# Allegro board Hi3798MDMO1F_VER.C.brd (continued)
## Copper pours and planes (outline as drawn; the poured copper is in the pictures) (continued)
1V1_CORE on BOTTOM (solid shape): 85.54,35.51 88.44,35.51 88.57,35.38 88.57,32.83 88.49,32.76 84.81,32.76 84.66,32.91 83.26,32.91 82.96,33.22 82.96,33.34 84.58,33.34 84.58,33.72 84.2,33.72 84.2,33.34 82.96,33.34 82.96,36.24 81.66,37.53 81.66,37.99 81.74,38.07 82.98,38.07
1V1_CPU on TOP (solid shape): 101.78,58.11 101.78,53.99 101.44,53.65 89.83,53.65 89.28,53.1 88.7,53.1 88.16,52.57 86.13,52.57 85.88,52.32 85.5,52.32 84.99,51.81 83.21,51.81 82.93,51.53 82.73,51.53 82.63,51.63 82.63,52.62 82.76,52.76 82.79,52.75 82.84,52.74 82.89,52.74 82.94,52.75 82.98,52.77 83.03,52.79 83.05,52.8 84.73,52.8 84.76,52.82 84.76,52.9 88.01,52.9 88.01,53.28 87.63,53.28 87.63,52.9 87.38,52.9 87.38,53.28 86.61,53.28 86.61,52.9 86.36,52.9 86.36,53.28 85.98,53.28 85.98,52.9 84.76,52.9 84.76,53.36 84.71,53.41 83.04,53.41 83.01,53.43 82.96,53.44 82.91,53.45 82.87,53.46 82.82,53.45 82.77,53.45 82.65,53.56 82.65,53.84 82.8,53.99 84.73,53.99 84.81,54.07 84.81,54.83 84.91,54.93 86.77,54.93 87.81,55.98 94.59,55.98 94.72,56.1 94.72,58.72 94.89,58.89 100.99,58.89
1V1_CPU on BOTTOM (solid shape): 99.14,56.12 99.14,56.12 99.32,55.95 99.32,53.87 99.09,53.64 93.75,53.64 93.6,53.79 93.6,54.81 97.28,54.81 97.28,55.19 96.9,55.19 96.9,54.81 93.6,54.81 93.6,55.57 93.65,55.62 97.46,55.62 97.66,55.82 97.66,56.58 97.79,56.71 98.55,56.71
1V1_CPU on BOTTOM (solid shape): 86.44,54.86 86.44,52.25 86.33,52.15 85.86,52.15 85.81,52.2 85.77,52.23 85.72,52.25 85.67,52.26 85.62,52.27 85.57,52.27 85.52,52.27 85.47,52.25 85.43,52.23 85.39,52.2 85.35,52.17 85.32,52.13 85.29,52.09 85.27,52.04 85.25,51.99 83.29,51.99 82.88,51.58 81.84,51.58 81.79,51.63 81.79,51.76 82.55,51.76 82.55,52.14 82.17,52.14 82.17,51.76 81.79,51.76 81.79,52.39 84.2,52.39 84.2,52.77 83.57,52.77 83.57,52.39 81.79,52.39 81.79,52.69 81.84,52.74 83.01,52.74 83.16,52.9 86.11,52.9 86.11,53.54 85.73,53.54 85.73,52.9 83.16,52.9 83.22,52.95 83.22,53.25 83.01,53.46 81.84,53.46 81.79,53.51 81.79,53.54 84.58,53.54 84.58,53.79 86.11,53.79 86.11,54.42 85.73,54.42 85.73,53.79 84.58,53.79 84.58,53.92 84.2,53.92 84.2,53.54 81.79,53.54 81.79,53.79 82.55,53.79 82.55,53.92 82.17,53.92 82.17,53.79 81.79,53.79 81.79,54.02 81.86,54.09 83.26,54.09 83.49,54.32 84.45,54.32 84.47,54.34 84.9,54.34 85.45,54.88 86.41,54.88
1V5_DDR3 on TOP (solid shape): 16.11,60.41 16.71,59.81 16.71,53.61 16.36,53.26 13.8,53.26 13.74,53.32 13.74,55.07 16.28,55.07 16.28,55.32 15.93,55.32 15.93,55.07 13.74,55.07 13.74,55.57 16.26,55.57 16.26,55.95 15.88,55.95 15.88,55.57 13.74,55.57 13.74,56.05 13.56,56.23 13.56,60.14 13.83,60.41 15.29,60.41
1V5_DDR3 on TOP (solid shape): outline of 129 points within 56.67,35.04 81.53,58.13
1V5_DDR3 on BOTTOM (solid shape): outline of 582 points within 14.99,30.55 59.41,63.83
3V3 on TOP (solid shape): 127.89,51.3 127.89,47.67 127.89,47.66 127.89,27.63 125.48,25.21 125.48,20.14 125.22,19.89 123.57,19.89 123.41,20.06 123.41,25.66 125.68,27.94 125.68,49.93 122.71,52.9 122.71,53.23 124.08,54.6 124.59,54.6
3V3 on TOP (solid shape): 114.45,57.45 114.45,55.24 114.38,55.16 108.62,55.16 108.43,55.35 108.43,55.82 109.22,55.82 109.22,56.2 108.84,56.2 108.84,55.82 108.43,55.82 108.43,56.43 108.06,56.79 108.06,57.58 108.13,57.65 114.25,57.65
3V3 on TOP (solid shape): 86.85,24.29 86.85,23.18 86.7,23.03 86.18,23.03 86.08,22.93 86.08,22.81 86.09,22.8 86.09,22.03 85.85,21.8 85.09,21.8 84.97,21.67 82.58,21.67 82.51,21.74 82.33,21.91 82.33,22.17 85.57,22.17 85.57,22.55 85.32,22.55 85.32,22.17 82.33,22.17 82.33,24.25 82.48,24.4 86.74,24.4
3V3 on TOP (solid shape): 15.31,68.89 15.31,66.93 14.92,66.54 12.47,66.54 12.04,66.11 12.04,61.39 11.94,61.29 10.16,61.29 10.04,61.41 11.68,61.41 11.68,61.79 11.3,61.79 11.3,61.41 10.04,61.41 8.76,62.69 6.86,62.69 6.48,62.31 6.48,57.86 7.11,57.23 7.11,56.47 6.99,56.34 5.21,56.34 4.32,55.45 4.32,47.96 4.06,47.7 2.03,47.7 1.78,47.96 1.78,63.58 4.19,65.99 7.91,65.99 11.04,69.12 15.07,69.12
3V3 on TOP (solid shape): 117.22,17.73 117.22,16.59 116.84,16.21 112.78,16.21 110.49,13.92 75.95,13.92 75.31,13.29 72.52,13.29 72.13,13.67 72.13,15.83 72.64,16.33 74.3,16.33 75.06,17.1 75.06,18.19 75.18,18.31 76.63,18.31 78.61,16.33 109.59,16.33 109.59,16.34 109.6,16.33 109.73,16.33 111.12,17.73 116.59,17.73 116.59,18.11 116.33,18.11 116.33,17.73 116.08,17.73 116.08,18.11 115.82,18.11 115.82,17.73 111.12,17.73 111.89,18.49 116.46,18.49
3V3 on BOTTOM (solid shape): 125.2,54.02 125.2,53.56 123.79,52.15 123.38,52.15 119.84,55.69 114.91,55.69 114.38,55.16 113.21,55.16 113.11,55.26 113.11,57.24 113.25,57.38 121.83,57.38
3V3 on BOTTOM (solid shape): 84.35,22.83 84.35,17.39 84.91,16.83 84.91,15.4 84.71,15.19 82.17,15.19 82.02,15.34 82.02,16.78 82.75,17.52 82.75,22.88 82.83,22.95 84.23,22.95
3V3 on BOTTOM (solid shape): 125.49,21.45 125.49,20.3 125.49,20.3 125.49,18.06 125.06,17.63 118.52,17.63 117.03,16.15 115.44,16.15 114.88,16.71 114.88,18.23 117.3,20.64 123.22,20.64 123.42,20.85 123.42,21.48 123.55,21.61 125.32,21.61
3V3 on BOTTOM (solid shape): 4.83,48.97 4.83,46.31 3.81,45.29 3.81,34.24 23.11,14.94 70.61,14.94 71.37,15.7 73.53,15.7 73.79,15.45 73.79,13.54 73.15,12.91 21.98,12.91 1.27,33.61 1.27,48.08 2.41,49.23 4.57,49.23
3V3_IR on TOP (solid shape): 127.39,18.62 128.53,18.62 128.78,18.37 128.78,11.94 128.57,11.73 127.06,11.73 126.68,12.11 126.68,17.04 126.12,17.6 124.72,17.6 124.59,17.73 124.59,17.85 127.89,17.85 127.89,18.23 127.51,18.23 127.51,17.85 125.48,17.85 125.48,18.23 125.09,18.23 125.09,17.85 124.59,17.85 124.59,18.37 124.72,18.49 125.36,18.49 125.86,19 127.01,19
3V3_MOS on TOP (solid shape): 123.95,75.51 123.95,72.71 123.83,72.59 122.81,72.59 122.68,72.71 122.68,75.51 122.81,75.63 123.83,75.63
3V3_MOS on TOP (solid shape): 80.14,56.2 80.14,41.6 79.5,40.96 70.1,40.96 69.98,41.09 69.98,41.98 70.23,42.23 77.72,42.23 77.98,42.49 77.98,54.68 77.47,55.19 65.41,55.19 65.15,55.44 65.15,56.84 79.5,56.84
3V3_MOS on TOP (solid shape): 118.62,64.58 118.62,55.79 119.61,54.81 119.61,54.02 119.3,53.71 118.01,53.71 117.09,54.63 117.09,63.69 117.09,63.69 113.25,67.53 112.3,67.53 112.04,67.79 112.04,68.85 112.21,69.02 114.18,69.02
3V3_MOS on TOP (solid shape): 124.76,47.67 124.76,32.63 108.72,16.59 78.74,16.59 76.64,18.69 74.07,18.69 73.99,18.76 73.99,20.26 74.3,20.57 77.56,20.57 80.02,18.1 85.7,18.1 85.78,18.1 85.85,18.1 88.04,18.1 88.11,18.1 88.18,18.1 90.4,18.1 90.47,18.1 90.55,18.1 92.89,18.1 92.96,18.1 93.04,18.1 95.08,18.1 95.15,18.1 95.22,18.1 108.13,18.1 122.58,32.56 122.58,47.67 122.73,47.82 124.61,47.82
3V3_MOS on BOTTOM (solid shape): 66.67,57.85 66.67,56.89 66.85,56.71 66.85,56.36 66.78,56.28 65.63,56.28 65.58,56.33 65.58,56.71 65.81,56.94 65.81,57.8 65.89,57.88 66.65,57.88
3V3_MOS on BOTTOM (solid shape): 69.34,57.83 69.34,56.86 69.52,56.69 69.52,56.33 69.44,56.25 68.3,56.25 68.25,56.3 68.25,56.69 68.48,56.91 68.48,57.78 68.55,57.85 69.32,57.85
3V3_MOS on BOTTOM (solid shape): 71.35,41.29 71.35,40.25 71.22,40.12 68.86,40.12 68.81,40.18 68.81,41.32 68.94,41.45 71.2,41.45
3V3_MOS on BOTTOM (solid shape): 79.63,42.11 79.63,41.09 79.5,40.96 77.85,40.96 77.6,41.22 77.6,41.34 78.61,41.34 78.61,41.72 78.23,41.72 78.23,41.34 77.6,41.34 77.6,42.11 77.85,42.36 79.38,42.36
3V3_MOS on BOTTOM (solid shape): 120.95,53.33 120.95,48.58 121.21,48.33 124.64,48.33 124.79,48.18 124.79,46.55 124.51,46.27 113.04,46.27 112.85,46.45 112.85,47.77 113.44,48.35 118.47,48.35 118.77,48.66 118.77,53.08 117.96,53.89 117.96,54.76 118.16,54.96 119.33,54.96
3V3_MOS on BOTTOM (solid shape): 74.35,57.57 74.35,56.94 74.57,56.71 74.57,56.38 74.47,56.28 73.48,56.28 73.36,56.41 73.36,56.74 73.46,56.84 74.17,56.84 74.17,57.22 73.91,57.22 73.91,56.84 73.46,56.84 73.69,57.07 73.69,57.52 73.76,57.6 74.32,57.6
3V3_MOS on BOTTOM (solid shape): 83.82,48.76 83.82,48.25 83.79,48.23 83.21,48.23 82.47,47.49 79.65,47.49 79.5,47.64 79.5,48.23 79.6,48.33 82.35,48.33 82.47,48.46 83.44,48.46 83.44,48.58 83.06,48.58 83.06,48.46 82.47,48.46 82.83,48.81 83.77,48.81
3V3_MOS on BOTTOM (solid shape): 113.58,68.96 113.58,67.52 113.17,67.11 111.75,67.11 110.85,68.01 101.22,68.01 90.79,57.57 88.01,57.57 86.82,56.38 86.82,55.87 86.77,55.82 85.62,55.82 85.17,55.36 80.87,55.36 80.42,54.91 78.97,54.91 78.77,55.11 78.77,55.95 79.2,56.38 80.57,56.38 81.1,56.91 81.1,57.75 81.13,57.78 81.89,57.78 82.02,57.65 82.02,56.51 82.23,56.29 84.98,56.29 87.71,59.02 89.19,59.02 99.96,69.78 112.75,69.78
3V3_MOS_FLASH on TOP (solid shape): outline of 289 points within 98.93,34.31 115.48,47
3V3_MOS_FLASH on BOTTOM (solid shape): 115.19,45.93 115.19,43.77 114.68,43.26 111.59,43.26 111.41,43.44 111.41,45.2 111.68,45.47 113.89,45.47 114.43,46 115.11,46
3V3_MOS_FLASH on BOTTOM (solid shape): 102.05,34.97 102.05,34.61 101.96,34.51 100.61,34.51 98.22,32.12 98.22,28.34 98.55,28.01 104.52,28.01 104.52,28.39 104.27,28.39 104.27,28.01 104.01,28.01 104.14,28.14 104.14,28.64 104.27,28.77 104.65,28.77 104.78,28.64 104.78,27.5 104.65,27.37 104.01,27.37 103.89,27.25 103.89,25.09 104.19,24.78 107.88,24.78 108.08,24.59 108.08,24.21 107.82,23.95 98.22,23.95 97.2,24.98 97.2,26.99 103.51,26.99 103.51,27.37 103.12,27.37 103.12,26.99 97.2,26.99 97.2,32.93 99.34,35.07 101.95,35.07
3V3_WIFI on TOP (solid shape): 14.4,38.61 14.4,36.92 12.14,34.66 9.78,34.66 9.51,34.93 9.51,35.9 9.74,36.12 11.88,36.12 12.75,36.99 12.75,38.55 12.99,38.78 13.13,38.78 13.13,38.79 14.23,38.79
3V3_WIFI on BOTTOM (solid shape): 7.84,44.24 7.84,37.46 9.12,36.17 11.81,36.17 12.46,35.51 12.46,34.37 12.81,34.02 14.18,34.02 14.36,33.83 14.36,32.96 14.07,32.67 11.56,32.67 10.31,33.93 7.84,33.93 6.1,35.67 6.1,44.24 6.54,44.68 7.4,44.68
5V0 on TOP (solid shape): 21.28,79.82 21.28,78.8 22.2,77.87 24.71,77.87 25.33,77.26 25.33,73.58 26.77,72.13 26.77,68.26 26.56,68.05 24.21,68.05 23.88,68.38 23.88,70.27 24.77,71.16 24.77,72.26 23.88,73.14 23.88,75.51 23.75,75.63 22.23,75.63 22.08,75.49 22.08,73.66 21.9,73.48 21.31,73.48 21.29,73.49 21.24,73.5 21.19,73.51 21.13,73.5 21.08,73.49 21.06,73.48 20.75,73.48 20.49,73.22 20.49,70.65 19.61,70.65 19.61,70.65 19.5,70.65 19.5,75.13 20.32,75.13 20.32,75.51 19.94,75.51 19.94,75.13 19.5,75.13 19.5,75.55 18.63,76.43 14.49,76.43 14.34,76.58 14.34,76.9 17.14,76.9 17.14,77.16 16.89,77.16 16.89,76.9 14.34,76.9 14.34,80.38 14.61,80.65 20.45,80.65
5V0_MOS on TOP (solid shape): 30.61,67.64 30.61,66.25 30.1,65.74 26.67,65.74 26.42,65.99 26.42,67.26 26.67,67.52 28.57,67.52 28.96,67.9 30.35,67.9
5V0_MOS on TOP (solid shape): 90.78,77.84 90.78,76.01 90.4,75.63 88.27,75.63 87.74,76.15 87.74,77.3 87.78,77.34 89.33,77.34 89.89,77.89 90.73,77.89
5V0_MOS on BOTTOM (solid shape): 87.7,89.44 87.7,86.9 89.04,85.55 89.05,85.55 89.45,85.15 89.45,85.15 91.75,82.85 91.75,80.48 92,80.23 92,76.83 90.93,75.76 90.93,73.35 90.81,73.22 89.92,73.22 89.79,73.35 89.79,76.65 90.74,77.6 90.74,77.96 91.44,77.96 91.44,78.31 91.19,78.31 91.19,77.96 90.74,77.96 90.74,78.56 91.44,78.56 91.44,78.9 91.19,78.9 91.19,78.56 90.74,78.56 90.74,80.67 90.73,80.67 90.73,82.45 86.61,86.57 86.61,88.97 86.22,89.37 68.31,89.37 68.31,89.37 67.19,89.37 64.01,86.18 64.01,77.02 61.09,74.1 61.08,74.1 60.33,73.35 58.94,71.96 57.66,71.96 56.01,70.31 45.59,70.31 44.32,71.58 42.05,71.58 38.32,67.85 32.47,67.85 31.11,66.5 29.21,66.5 28.96,66.75 28.96,67.64 31.06,69.75 37.67,69.75 40.9,72.98 44.83,72.98 46.23,71.58 55.5,71.58 57.15,73.23 58.55,73.23 62.61,77.29 62.61,86.95 66.03,90.37 86.77,90.37
AVDD11_PLL012 on BOTTOM (solid shape): 83.87,43.3 83.87,42.64 83.85,42.61 83.07,42.61 83.05,42.63 83,42.66 82.94,42.67 82.89,42.68 82.83,42.68 82.78,42.67 82.72,42.66 82.67,42.63 82.63,42.6 82.59,42.56 82.57,42.54 80.16,42.54 80.09,42.61 80.09,42.87 83.57,42.87 83.57,43.12 83.19,43.12 83.19,42.87 80.09,42.87 80.09,42.99 82.42,42.99 82.42,43.12 82.04,43.12 82.04,42.99 81.79,42.99 81.79,43.12 81.41,43.12 81.41,42.99 80.09,42.99 80.09,43.33 80.14,43.38 83.79,43.38
AVDD33_PLL01 on BOTTOM (solid shape): 83.9,42.13 83.9,41.42 83.69,41.22 81.25,41.22 81.08,41.04 80.42,41.04 80.37,41.09 80.37,41.47 83.44,41.47 83.44,41.72 83.19,41.72 83.19,41.47 82.42,41.47 82.42,41.6 82.04,41.6 82.04,41.47 81.79,41.47 81.79,41.6 81.41,41.6 81.41,41.47 80.37,41.47 80.37,41.95 80.42,42 82.66,42 82.68,41.99 82.73,41.97 82.78,41.95 82.83,41.94 82.88,41.94 82.93,41.95 82.98,41.97 83.03,41.99 83.07,42.02 83.11,42.05 83.15,42.09 83.17,42.13 83.19,42.16 83.87,42.16
AVDD33_USB2 on BOTTOM (solid shape): 83.85,50.87 83.85,50.34 83.82,50.31 82.78,50.31 82.14,49.68 82.14,48.99 81.33,48.99 81.31,49.01 81.31,49.75 81.71,50.16 81.71,51.02 81.75,51.06 83.65,51.06
GND on TOP (solid shape): 35.56,80.54 35.56,79.01 35.61,78.96 37.26,78.96 37.32,78.9 37.32,78.21 37.26,78.15 35.58,78.15 35.58,78.15 34.61,78.15 33.23,79.53 33.23,80.6 33.27,80.64 35.46,80.64
GND on TOP (solid shape): 105.94,49.3 105.94,49.22 105.66,48.94 105.58,48.94 104.69,49.82 92.26,49.82 90.68,48.24 85.22,48.24 85.04,48.42 85.04,48.67 85.12,48.75 86,48.75 86,48.48 86.92,48.48 86.92,48.56 87.66,48.56 87.66,48.75 90.43,48.75 92.01,50.33 104.91,50.33
GND on TOP (solid shape): 106.57,50.08 106.57,49.69 106.43,49.55 106.24,49.55 105.07,50.71 91.85,50.71 90.27,49.13 87.66,49.13 87.66,49.32 86.94,49.32 86.94,49.33 86.92,49.33 86.92,49.4 86,49.4 86,49.13 85,49.13 84.91,49.22 84.91,49.48 85.12,49.69 90.17,49.69 91.71,51.22 105.42,51.22
GND on TOP (solid shape): 96.24,43.94 97.02,43.17 97.02,31.07 96.42,30.47 96.42,25.74 96.42,24.6 96.29,24.48 96.12,24.48 95.94,24.66 95.94,27.5 95.94,27.51 95.94,43.44 94.72,44.66 85.21,44.66 85.12,44.72 85.14,44.83 85.5,45.19 94.99,45.19
GND on TOP (solid shape): 98.55,72.87 101.18,72.87 101.96,72.09 101.96,71.52 101.98,71.49 103.71,71.49 103.73,71.52 103.73,72.08 104.51,72.87 106.86,72.87 106.91,72.81 106.91,70.96 106.81,70.86 106.35,70.86 106.2,71.01 101.59,71.01 100.89,71.01 100.89,71.01 99.44,71.01 99.44,72 98.2,72 98.2,72.01 97.51,72.01 97.38,72.15 97.38,72.26 97.28,72.36 97.28,72.59 98.17,72.59 98.17,72.71 97.66,72.71 97.66,72.59 97.28,72.59 97.28,72.99 97.36,73.07 98.35,73.07
GND on TOP (solid shape): 119.4,67.59 119.44,67.57 119.46,67.54 119.46,65.5 120.16,65.5 120.2,65.49 120.21,65.45 120.21,63.91 120.2,63.87 120.16,63.85 119.45,63.85 119.41,63.87 119.4,63.91 119.4,64.81 118.82,65.39 118.82,66.29 118.82,66.31 118.84,66.33 119.01,66.65 118.84,66.96 118.82,66.98 118.82,67.01 118.82,67.05 119.35,67.59
GND on TOP (solid shape): 44.57,48.95 44.69,48.85 44.84,48.81 44.91,48.78 44.94,48.72 45.07,48.5 45.33,48.45 45.41,48.43 45.45,48.35 45.45,48.31 43.89,46.74 43.06,46.74 42.97,46.8 42.99,46.92 43.56,47.48 43.77,47.48 43.89,47.6 43.9,47.6 44.26,47.95 44.26,48.46 44.24,48.48 44.24,48.84 44.35,48.95
GND on TOP (solid shape): 55.35,55.71 57.58,55.71 57.69,55.6 57.69,55.4 57.57,55.29 54.56,55.29 53.81,54.54 53.48,54.54 53.42,54.6 53.34,54.64 53.27,54.71 53.3,54.81 53.36,54.86 53.37,54.87 53.46,55.36 52.97,55.27 52.96,55.26 52.79,55.09 52.77,55.08 52.66,55.03 52.57,54.94 52.32,54.94 52.24,55.02 52.24,56.03 52.62,56.4 54.66,56.4
GND on TOP (solid shape): 35.59,52.54 35.69,52.48 35.66,52.37 29.91,46.61 29.85,46.6 29.82,46.65 27.85,46.65 27.84,46.65 27.57,46.67 27.36,46.5 26.46,46.5 23.38,43.41 23.38,33.22 34.24,22.37 64.29,22.37 73.5,31.57 73.66,31.57 73.8,31.44 73.8,31.15 64.51,21.86 33.38,21.86 22.87,32.37 22.87,44.27 25.86,47.26 27.36,47.26 27.56,47.09 27.83,47.1 27.92,47.08 27.96,47 27.96,46.99 29.69,46.99 29.69,47.26 29.87,47.26 35.16,52.54
GND on TOP (solid shape): 57.69,42.01 57.69,41.79 57.59,41.69 55.52,41.69 53.87,40.05 53.87,38.18 53.82,38.13 53.48,38.13 53.42,38.19 53.34,38.23 53.27,38.3 53.3,38.4 53.35,38.45 53.53,38.62 53.53,38.87 53.53,39.1 53.25,39.62 52.97,39.1 52.97,38.87 52.96,38.85 52.79,38.68 52.77,38.67 52.64,38.61 52.55,38.48 52.35,38.48 52.24,38.59 52.24,39.7 54.65,42.11 57.59,42.11
GND on TOP (solid shape): outline of 91 points within 84.84,25.48 94.79,43.52
GND on TOP (solid shape): 27.89,82.2 27.89,81.74 27.8,81.65 27.8,81.61 27.8,81.6 27.77,81.54 27.77,81.48 27.77,80.9 27.77,80.84 27.8,80.78 27.8,80.55 27.77,80.49 27.77,80.43 27.77,79.85 27.77,79.78 27.8,79.73 27.8,79.72 27.8,79.67 27.89,79.59 27.89,73.95 31.26,70.58 37.43,70.58 44.35,63.66 57.79,63.66 62.29,68.17 69.18,68.17 72.85,64.5 72.85,63.1 72.8,63.05 72.72,63.04 72.23,63.53 72.21,63.55 72.21,64.39 68.94,67.66 62.53,67.66 58.01,63.14 44.13,63.14 37.22,70.05 30.77,70.05 27.13,73.69 27.13,79.6 27.13,79.61 27.21,79.69 27.21,79.72 27.22,79.73 27.24,79.78 27.25,79.85 27.25,80.43 27.24,80.49 27.22,80.55 27.22,80.78 27.24,80.84 27.25,80.9 27.25,81.48 27.22,81.6 27.13,81.69 27.08,81.71 27.02,81.77 27.02,82.32 27.27,82.58 27.27,82.64 27.45,82.64
GND on TOP (solid shape): 104.67,49.3 104.67,48.74 104.62,48.68 103.96,48.68 103.91,48.63 103.91,46.75 104,46.66 104.01,46.65 104.01,46.4 104.39,46.02 106.94,46.02 106.95,46.02 107.32,46.19 107.3,46.59 107.29,46.7 107.38,46.76 109.5,46.76 109.5,45.45 109.24,45.18 101.8,45.18 101.14,44.52 100.54,44.52 100.54,44.52 99.93,44.52 98.51,45.94 98.51,46.76 100.29,46.76 100.38,46.72 100.39,46.63 100.76,46.14 101.12,46.63 101.12,46.68 101.15,46.73 103.56,46.73 103.61,46.78 103.61,48.63 103.58,48.66 102.57,48.66 102.49,48.74 102.49,49.37 102.56,49.44 104.53,49.44
GND on TOP (solid shape): 30.98,82.16 30.98,81.61 30.97,81.6 30.95,81.54 30.94,81.48 30.94,80.9 30.95,80.84 30.97,80.78 30.97,80.56 30.95,80.48 30.94,80.43 30.94,79.85 30.95,79.78 30.97,79.73 30.98,79.71 30.98,79.65 31.06,79.56 31.06,75.48 31.06,75.47 33.52,73.02 38.42,73.02 45.31,66.13 56.82,66.13 56.83,66.13 61.3,70.6 70.2,70.6 75.26,65.54 75.26,61.98 75.24,61.95 75.13,61.95 74.78,62.31 74.78,65.32 74.78,65.33 69.99,70.12 61.54,70.12 57.01,65.6 45.69,65.6 45.12,65.6 38.22,72.5 38.21,72.51 32.7,72.51 30.29,74.92 30.28,74.93 30.28,79.62 30.3,79.64 30.39,79.72 30.42,79.85 30.42,80.43 30.42,80.49 30.39,80.55 30.39,80.76 30.42,80.84 30.42,80.9 30.42,81.48 30.39,81.6 30.3,81.69 30.3,81.69 30.19,81.8 30.19,82.42 30.27,82.51 30.27,82.62 30.52,82.62
GND on TOP (solid shape): 46.27,57.65 46.27,55.54 46.22,55.46 46.13,55.44 46.09,55.45 46.01,55.45 45.38,56.09 45.38,57.76 43.74,59.39 32.19,59.39 30.1,57.29 29.82,57.29 29.82,57.45 27.85,57.45 27.84,57.45 27.57,57.47 27.36,57.29 26.21,57.29 18.53,49.61 18.53,30.43 31.44,17.52 66.47,17.52 79.72,30.76 79.72,33.71 79.61,33.81 79.61,34.48 79.7,34.56 79.94,34.56 80.03,34.48 80.03,33.94 79.88,33.65 80.04,33.37 80.09,33.29 80.04,33.2 79.92,32.71 80.41,32.59 80.65,32.59 80.83,32.41 80.83,31.14 66.7,17.01 31.22,17.01 18.02,30.21 18.02,49.83 26.11,57.93 27.36,57.93 27.57,57.75 27.84,57.77 27.85,57.77 29.82,57.77 29.82,57.93 30.05,57.93 32.02,59.9 44.02,59.9
GND on TOP (solid shape): 28.77,82.61 28.84,82.69 28.95,82.67 29.48,82.14 29.48,81.62 29.44,81.55 29.43,81.47 29.43,80.91 29.44,80.84 29.47,80.78 29.47,80.76 29.47,80.56 29.47,80.55 29.44,80.49 29.43,80.42 29.43,79.86 29.46,79.74 29.53,79.65 29.54,79.65 29.57,79.6 29.57,74.64 32.4,71.8 37.91,71.8 44.82,64.89 57.3,64.89 57.31,64.89 61.81,69.38 61.83,69.41 69.69,69.41 74.07,65.03 74.07,62.01 74.27,61.81 74.29,61.7 74.2,61.64 73.56,61.64 73.56,64.79 73.56,64.8 69.47,68.88 62,68.88 57.49,64.38 44.64,64.38 37.73,71.29 31.55,71.29 28.61,74.23 28.6,74.24 28.6,79.56 28.71,79.67 28.71,79.71 28.72,79.72 28.75,79.79 28.76,79.86 28.76,80.42 28.75,80.49 28.73,80.55 28.72,80.56 28.72,80.76 28.73,80.78 28.75,80.84 28.76,80.91 28.76,81.47 28.72,81.6 28.62,81.69 28.62,81.7 28.58,81.74 28.58,82.41
GND on TOP (solid shape): 44.67,57.3 44.67,54.84 44.48,54.65 44.41,54.65 44.37,54.64 44.28,54.66 44.24,54.74 44.24,56.68 42.86,58.07 32.73,58.07 30.17,55.52 29.82,55.52 29.82,55.67 27.85,55.67 27.84,55.67 27.57,55.69 27.36,55.52 26.34,55.52 19.85,49.03 19.85,31.04 32.05,18.84 65.86,18.84 77.71,30.68 77.71,33.76 77.61,33.86 77.61,34.46 77.72,34.56 77.93,34.56 78.03,34.47 78.03,33.94 77.88,33.65 78.04,33.37 78.09,33.29 78.04,33.2 77.92,32.71 78.41,32.59 78.74,32.59 78.83,32.5 78.83,31.05 66.11,18.33 31.8,18.33 19.34,30.79 19.34,49.25 26.49,56.4 26.72,56.4 27.05,56.21 27.38,56.4 27.84,56.4 27.84,56.25 29.82,56.25 29.82,56.4 30.38,56.4 32.55,58.57 43.39,58.57
GND on TOP (solid shape): outline of 164 points within 122.63,11.5 126.43,17.34
GND on TOP (solid shape): 39.82,54.46 40.31,54.46 40.86,53.91 40.88,53.8 40.79,53.74 40.22,53.74 39.76,54.21 34.43,54.21 30.27,50.05 29.82,50.05 29.82,50.21 27.84,50.21 27.84,50.05 27.38,50.05 26.71,50.03 27.1,49.48 27.33,49.25 27.33,48.98 27.42,48.58 27.83,48.49 27.92,48.48 27.96,48.4 27.96,48.39 29.69,48.39 29.69,48.66 30.05,48.66 34.79,53.39 39.47,53.39 39.76,53.1 39.79,52.99 39.69,52.93 35,52.93 29.87,47.79 29.76,47.77 29.69,47.86 29.69,47.91 27.96,47.91 27.96,47.9 27.92,47.82 27.83,47.8 27.56,47.81 27.36,47.64 25.7,47.64 22.49,44.43 22.49,32.21 33.22,21.48 64.67,21.48 74.18,30.99 74.18,33.2 74.01,33.37 74.01,34.47 74.11,34.56 74.33,34.56 74.43,34.46 74.43,33.94 74.31,33.52 74.7,33.33 74.79,33.31 74.83,33.23 74.83,30.91 64.89,20.97 33,20.97 21.98,31.98 21.98,47.83 24.84,50.69 26.72,50.69 27.05,50.5 27.38,50.69 27.84,50.69 27.84,50.54 29.82,50.54 29.82,50.69 30.23,50.69 34.2,54.66 39.62,54.66
GND on TOP (solid shape): outline of 81 points within 102.62,35.5 105.99,39.36
GND on TOP (solid shape): 57.69,44.4 57.69,44.22 57.68,44.22 57.55,44.09 56.67,44.09 56.07,44.02 56.47,43.57 56.55,43.56 56.59,43.48 56.84,43.18 57.21,43.31 57.61,43.31 57.69,43.23 57.69,42.98 57.6,42.89 54.29,42.89 51.06,39.65 51.06,38.33 51.02,38.25 50.93,38.23 50.59,38.1 50.62,37.73 50.62,37.35 50.57,37.01 50.86,36.83 50.88,36.83 51.17,36.55 51.77,36.55 52.3,36.52 52.2,37.04 52.2,37.42 52.24,37.47 52.24,37.55 52.28,37.63 52.37,37.64 52.57,37.66 52.72,37.8 52.98,37.8 53.02,37.73 53.09,37.68 53.09,37.4 53.1,36.87 53.55,37.15 53.55,37.17 53.73,37.35 54.13,37.35 54.64,37.86 54.64,39.71 55.83,40.91 57.59,40.91 57.69,40.82 57.69,40.59 57.57,40.48 57.51,40.48 57.5,40.47 56.08,40.47 54.76,39.15 54.76,37.62 53.35,36.21 49.55,36.21 49.3,36.46 49.3,36.71 49.5,36.91 49.85,36.91 50.33,37.04 50.03,37.44 50.01,37.44 49.98,37.48 49.98,37.5 49.94,37.71 49.78,37.85 49.78,38.21 49.84,38.26 49.84,39.55 53.56,43.27 54.38,43.27 55.62,44.51 57.58,44.51
GND on TOP (solid shape): 57.69,58.01 57.69,57.76 57.61,57.69 57.2,57.69 56.83,57.82 56.58,57.52 56.54,57.44 56.46,57.42 56.05,56.99 56.64,56.91 57.57,56.91 57.69,56.79 57.69,56.62 57.68,56.62 57.55,56.49 55.74,56.49 55.07,57.17 52.13,57.17 51.06,56.1 51.06,54.74 51.02,54.66 50.93,54.64 50.56,54.45 50.73,54.07 50.73,54.06 50.79,54.01 50.82,53.91 50.75,53.84 50.57,53.42 51.01,53.29 51.04,53.31 51.46,52.9 51.77,52.9 52.3,52.87 52.2,53.39 52.2,53.77 52.46,54.04 52.62,54.1 52.73,54.23 52.73,54.23 52.96,54.23 53.03,54.13 53.14,54.06 53.14,53.83 53.08,53.29 53.55,53.56 53.55,53.58 53.73,53.76 54.13,53.76 54.88,54.51 57.69,54.51 57.69,54.1 57.58,54.1 57.5,54.02 55.13,54.02 53.66,52.56 49.63,52.56 49.28,52.91 49.28,53.14 49.45,53.32 49.85,53.32 50.33,53.45 50.03,53.85 50.01,53.85 49.98,53.89 49.98,53.91 49.92,54.14 49.73,54.27 49.73,54.56 49.84,54.67 49.84,56.14 51.81,58.11 57.59,58.11
GND on TOP (solid shape): outline of 341 points within 20.66,19.65 76.83,57.25
GND on TOP (solid shape): outline of 214 points within 23.76,22.75 73.23,52.21
GND on TOP (solid shape): outline of 10403 points within 0.51,10.62 129.62,93.41
GND on BOTTOM (solid shape): outline of 133 points within 104.08,39.18 109.13,46.22
GND on BOTTOM (solid shape): outline of 14933 points within 0.51,10.62 129.62,93.41
FE_3V3 on BOTTOM (solid shape): 67.98,60.65 67.98,58.53 67.97,58.51 65.91,58.51 65.82,58.6 65.82,59.82 65.94,59.94 66.34,59.94 66.4,59.89 66.4,59.38 66.47,59.3 67.36,59.3 67.44,59.38 67.44,60.65 67.46,60.67 67.96,60.67
HDMI_TX_1V1 on BOTTOM (solid shape): 75.46,60.65 75.46,59.86 75.56,59.76 75.57,59.76 75.67,59.66 76.28,59.66 76.3,59.63 76.3,58.54 76.43,58.41 77.04,58.41 77.14,58.31 77.14,58.08 77.29,57.93 77.95,57.93 77.98,57.9 77.98,57.4 77.95,57.37 75.13,57.37 74.93,57.57 74.93,57.6 77.6,57.6 77.6,57.73 77.22,57.73 77.22,57.6 74.93,57.6 74.93,58.37 75.02,58.46 75.26,58.46 75.34,58.54 75.34,59 75.95,59 75.95,59.25 75.56,59.25 75.56,59 75.34,59 75.34,59.43 75.29,59.48 74.96,59.48 74.83,59.61 74.83,60.01 75.18,60.01 75.18,60.39 75.06,60.39 75.06,60.01 74.83,60.01 74.83,60.7 74.85,60.72 75.39,60.72
HDMI_TX_3V3 on BOTTOM (solid shape): 74.12,60.7 74.12,59.91 74.32,59.71 74.32,57.88 74.3,57.85 73.76,57.85 73.74,57.88 73.74,58.23 74.04,58.23 74.04,58.87 73.91,58.87 73.91,58.23 73.74,58.23 73.74,59.48 73.6,59.62 73.6,59.63 73.56,59.66 73.56,60.01 73.91,60.01 73.91,60.39 73.79,60.39 73.79,60.01 73.56,60.01 73.56,60.7 73.58,60.72 74.09,60.72
Net_291 on BOTTOM (solid shape): 59.01,86.74 56.34,86.74 56.34,88.01 59.01,88.01
Net_292 on BOTTOM (solid shape): 47.45,86.74 44.78,86.74 44.78,88.01 47.45,88.01
Net_293 on BOTTOM (solid shape): 57.99,88.52 55.33,88.52 55.33,89.79 57.99,89.79
Net_294 on BOTTOM (solid shape): 46.44,88.52 43.77,88.52 43.77,89.79 46.44,89.79
USB01_1V1 on BOTTOM (solid shape): 71.3,60.72 71.3,60.04 71.96,59.38 72.82,59.38 72.87,59.33 72.87,58.67 72.85,58.64 71.48,58.64 71.42,58.69 71.42,58.87 72.52,58.87 72.52,59 71.76,59 71.76,58.87 71.42,58.87 71.42,59.17 70.79,59.81 70.79,60.01 71.12,60.01 71.12,60.39 70.99,60.39 70.99,60.01 70.79,60.01 70.79,60.7 70.8,60.73 70.81,60.74 70.84,60.75 71.27,60.75
USB01_3V3 on BOTTOM (solid shape): 69.52,60.85 69.52,60.83 69.55,60.83 69.62,60.75 70.26,60.75 70.28,60.72 70.28,60.22 70.26,60.19 69.7,60.19 69.44,59.94 69.44,59.66 69.34,59.56 69.34,58.59 69.32,58.57 68.5,58.57 68.49,58.58 68.49,60.39 69.82,60.39 69.82,60.55 69.47,60.55 69.47,60.39 68.49,60.39 68.49,60.91 68.53,60.95 69.42,60.95
USB03_VBUS on TOP (solid shape): 86.36,77.28 86.36,73.98 85.98,73.6 81.92,73.6 80.39,72.08 77.22,72.08 77.09,72.2 77.09,75.13 77.47,75.51 84.07,75.51 84.58,76.01 84.58,77.08 84.89,77.39 86.26,77.39
USB03_VBUS on BOTTOM (solid shape): 89.28,75.38 89.28,73.35 89.15,73.22 82.3,73.22 82.17,73.35 82.17,75.38 82.3,75.51 89.15,75.51
VDAC_3V3 on BOTTOM (solid shape): 80.92,60.72 80.92,60.24 80.85,60.17 80.85,59.5 80.42,59.07 80.42,56.97 80.39,56.94 79.63,56.94 79.6,56.96 79.6,59.05 79.93,59.37 79.96,59.38 80.2,59.47 80.32,59.69 80.37,59.73 80.37,60.72 80.39,60.75 80.9,60.75
$4N589 on TOP (solid shape): 12.51,60.32 12.51,56.65 12.31,56.46 8.51,56.46 8.36,56.61 8.36,57.35 8.67,57.67 8.94,57.67 9.52,58.25 9.52,59.82 10.1,60.4 12.42,60.4
$4N679 on TOP (solid shape): 105.36,57.7 107.01,57.7 107.04,57.68 107.04,54.35 106.88,54.2 103.1,54.2 102.92,54.37 102.92,58.01 103,58.08 104.98,58.08
$4N719 on TOP (solid shape): 87.58,31.62 87.58,27.68 86.85,26.95 86.85,25.34 86.79,25.28 86,25.28 85.83,25.45 85.83,26.34 85.62,26.55 85.62,31.59 85.73,31.69 87.5,31.69
$4N903 on TOP (solid shape): 23.62,72.33 23.62,71.32 23.5,71.19 22.99,71.19 22.48,71.7 22.48,72.33 22.61,72.46 23.5,72.46
$4N925 on TOP (solid shape): 19.07,74.09 19.07,73.9 19.07,70.58 19.01,70.53 18.29,70.53 18.16,70.65 18.16,72.58 17.88,72.85 16.84,72.85 16.44,72.46 16.44,71.91 15.86,71.32 11.24,71.32 10.84,71.73 10.84,74.38 11.28,74.82 18.35,74.82
$4N944 on TOP (solid shape): 15.8,86.99 15.82,86.99 15.88,86.94 15.88,82.03 15.73,81.89 14.49,81.89 13.84,81.24 13.84,77.15 13.1,76.41 11.67,76.41 11.05,77.03 11.05,85.35 11.05,85.35 11.05,86.55 11.72,87.22 15.57,87.22

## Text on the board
BOTTOM: HI3798MDMO1F VER.C ARTWORK BOTTOM
Ref Des/Silkscreen Bottom: HI3798MDMO1F VER.C SILKSCREEN BOTTOM
User.Comments: HI3798MDMO1F VER.C SOLDMASK TOP | HI3798MDMO1F VER.C SOLDMASK BOTTOM
TOP: HI3798MDMO1F VER.C ARTWORK TOP
Ref Des/Silkscreen Top: A | HI3798MDMO1F VER.C SILKSCREEN TOP | HI3798MDMO1F VER.C
DIMENSION: 1-plated oval slot:30X116mil | 1-plated oval slot:96x30mil | 1-plated oval slot:26x96mil | 2XOBLONG VIA 36X105MIL | 2XOBLONG VIA 118X87MIL | 2XOBLONG VIA 36X82MIL | 2XOBLONG VIA 60X32MIL | 3XOBLONG VIA 98X59MIL | 3XOBLONG VIA 47X98MIL | 2XOBLONG VIA 118X79MIL | OBLONG VIA 32X60MIL | (0,0) | HI3798MDMO1F VER.C | Notes3: | For this PN,Soldermask should be covered at all required location and | no red solder(copper color) is allowed at BGA area | HI3798MDMO1F VER.C DRILL CHART
DISPLAY_BOTTOM: HI3798MDMO1F VER.C PASTEMASK BOTTOM
DISPLAY_TOP: HI3798MDMO1F VER.C PASTEMASK TOP
BODY_CENTER: dia 3.5 | 61.97
User.12: 10 | 6 | 2 | 3 | 1 | 7 | 8 | 9 | PCB EDGE | 19 | 5 | 4 | J12 | S1 | A | dia 3.5 | 61.97 | 55 | BGA19X19 2-LAYERS
User.13: 10 | 6 | 2 | 3 | 1 | 7 | 8 | 9 | PCB EDGE | 19 | 5 | 4 | J12 | S1 | A | dia 3.5 | 55 | 61.97 | BGA19X19 2-LAYERS
User.20: FIGURE | SIZE | 8.0 | 10.0 | 12.0 | 20.0 | 22.0 | 32.0 | 36.0 | 38.0 | 40.0 | 45.0 | 52.0 | 142.0 | 43.0 | 71.0 | 135.0 | 60.0x32.0 | 82.0x36.0 | 96.0x26.0 | 96.0x30.0 | 98.0x47.0 | 98.0x59.0 | 105.0x36.0 | 116.0x30.0 | 118.0x79.0 | 118.0x87.0 | DRILL CHART: TOP to BOTTOM | ALL UNITS ARE IN MILS | PLATED | NON-PLATED | QTY | 423 | 1803 | 36 | 4 | 2 | 3 | 27 | 12 | 8 | 40 | 1
